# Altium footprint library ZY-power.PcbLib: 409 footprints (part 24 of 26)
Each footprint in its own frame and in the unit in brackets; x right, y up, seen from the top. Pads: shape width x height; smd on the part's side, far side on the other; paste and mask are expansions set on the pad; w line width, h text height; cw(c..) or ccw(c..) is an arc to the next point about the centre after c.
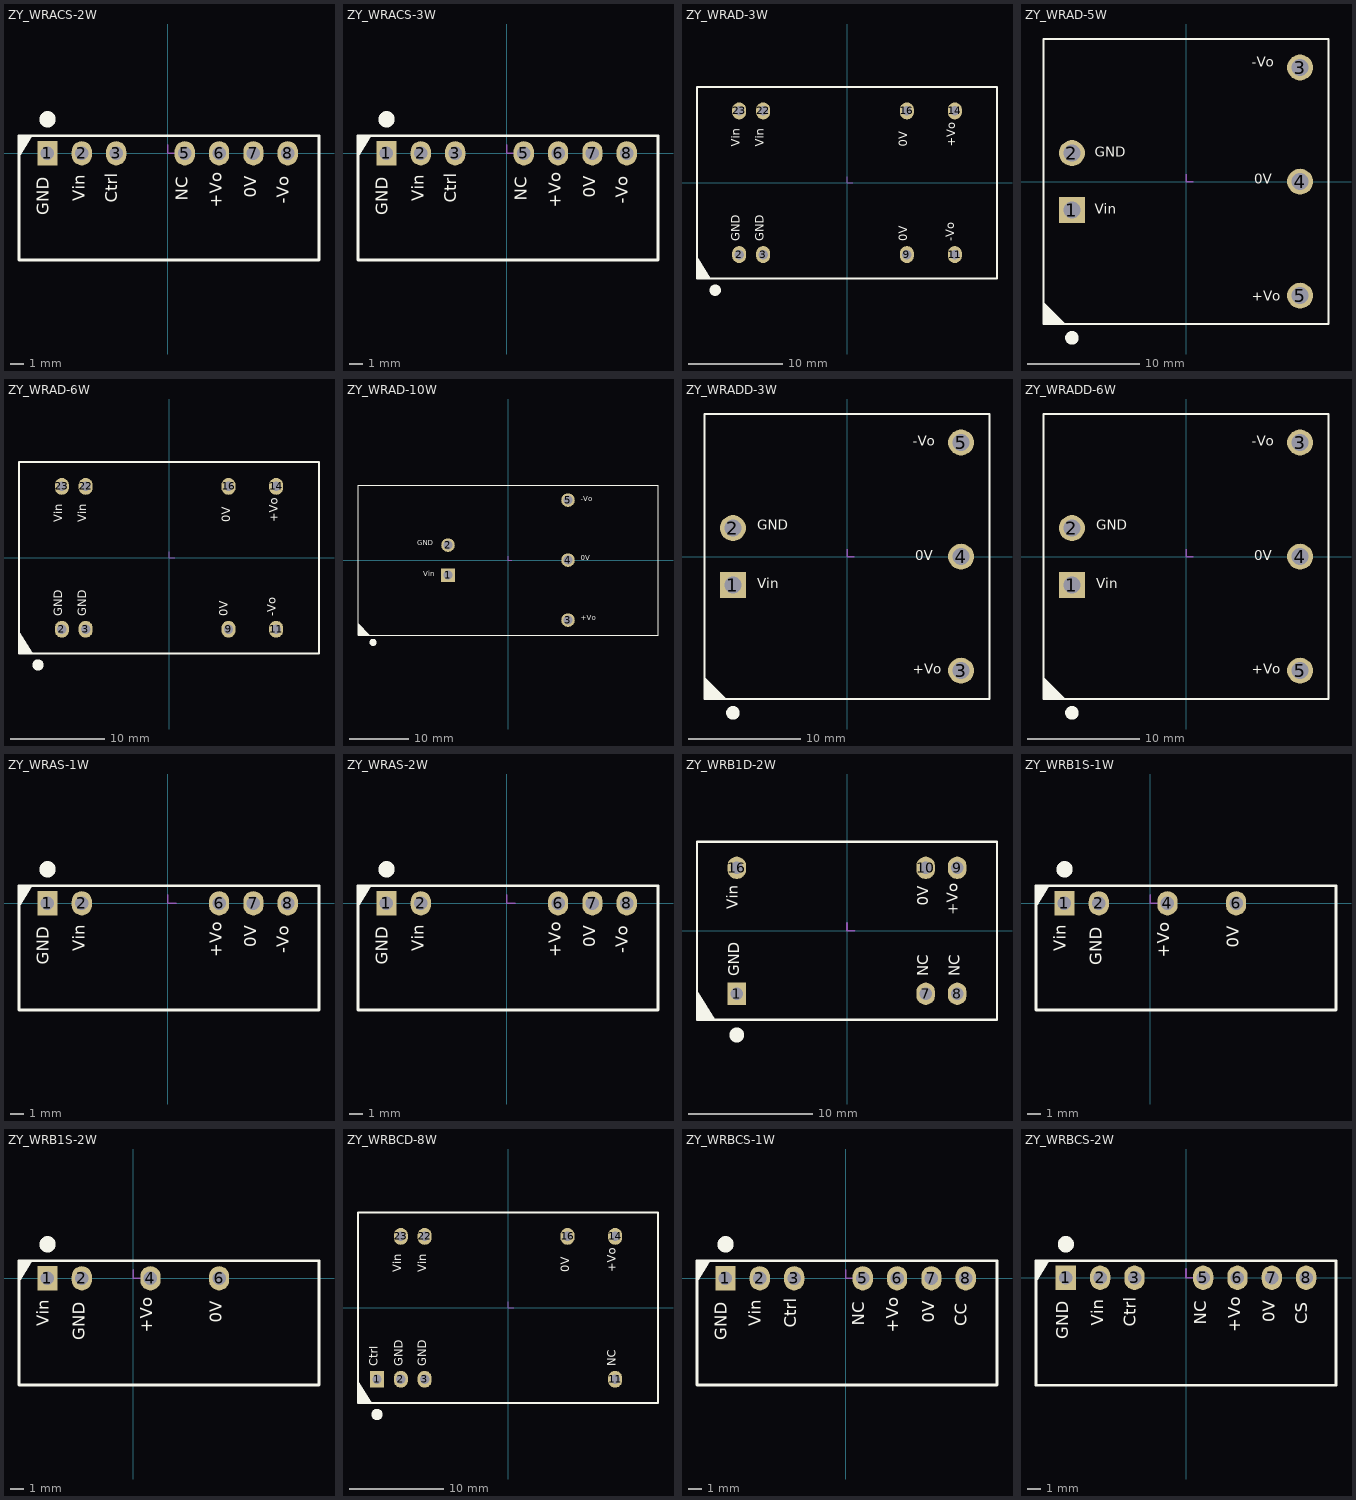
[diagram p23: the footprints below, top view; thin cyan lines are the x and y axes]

## ZY_WRACS-2W [mm]
pads (7):
  rect 1.5x1.8 hole 1: 1(-8.89,0)
  oval 1.5x1.8 hole 1: 2(-6.35,0) 3(-3.81,0) 5(1.27,0) 6(3.81,0) 7(6.35,0) 8(8.89,0)
Top Overlay:
  circle w1: c-8.89,2.52 r0.1
  region: -10.998,-0.29 -10.998,1.295 -10.005,1.295
  lines w0.2: 11.201,-7.899 -10.998,-7.899 -10.998,1.295 11.201,1.295 11.201,-7.874
  text "GND" at -8.509,-4.572 h1.52
  text "Vin" at -5.842,-3.562 h1.52
  text "Ctrl" at -3.429,-3.646 h1.52
  text "NC" at 1.778,-3.501 h1.52
  text "+Vo" at 4.318,-4.03 h1.52
  text "0V" at 6.858,-3.29 h1.52
  text "-Vo" at 9.271,-3.718 h1.52
Mechanical 15:
  lines w0.127: 0,0.635 0,0 0.635,0

## ZY_WRACS-3W [mm]
height 12.2
pads (7):
  rect 1.5x1.8 hole 1: 1(-8.89,0)
  oval 1.5x1.8 hole 1: 2(-6.35,0) 3(-3.81,0) 5(1.27,0) 6(3.81,0) 7(6.35,0) 8(8.89,0)
Top Overlay:
  circle w1: c-8.89,2.52 r0.1
  region: -10.998,-0.29 -10.998,1.295 -10.005,1.295
  lines w0.2: 11.201,-7.899 -10.998,-7.899 -10.998,1.295 11.201,1.295 11.201,-7.874
  text "-Vo" at 9.271,-3.718 h1.52
  text "0V" at 6.858,-3.29 h1.52
  text "+Vo" at 4.318,-4.03 h1.52
  text "NC" at 1.778,-3.501 h1.52
  text "Ctrl" at -3.429,-3.646 h1.52
  text "Vin" at -5.842,-3.562 h1.52
  text "GND" at -8.509,-4.572 h1.52
Mechanical 15:
  lines w0.127: 0,0.635 0,0 0.635,0

## ZY_WRAD-3W [mm]
pads (8):
  oval 1.5x1.8 hole 1: 2(-11.43,-7.62) 3(-8.89,-7.62) 9(6.35,-7.62) 11(11.43,-7.62) 14(11.43,7.62) 16(6.35,7.62) 22(-8.89,7.62) 23(-11.43,7.62)
Top Overlay:
  circle w1: c-13.97,-11.385 r0.1
  region: -15.9,-7.83 -15.9,-10.16 -14.44,-10.16
  lines w0.2: -15.9,-10.16 -15.9,10.16 15.9,10.16 15.9,-10.16 -15.9,-10.16
  text "Vin" at -11.049,3.81 h1.52
  text "Vin" at -8.509,3.81 h1.52
  text "0V" at 6.731,3.81 h1.52
  text "+Vo" at 11.811,3.81 h1.52
  text "-Vo" at 11.684,-6.223 h1.52
  text "0V" at 6.731,-6.223 h1.52
  text "GND" at -8.509,-6.223 h1.52
  text "GND" at -11.049,-6.223 h1.52
Mechanical 15:
  lines w0.127: 0,0.635 0,0 0.635,0

## ZY_WRAD-5W [mm]
height 11.7
pads (5):
  rect 2.3x2.3 hole 1.5: 1(-10.16,-2.54)
  round 2.3 hole 1.5: 2(-10.16,2.54) 3(10.16,10.16) 4(10.16,0) 5(10.16,-10.16)
Top Overlay:
  circle w1: c-10.16,-13.925 r0.1
  region: -12.7,-12.7 -10.725,-12.7 -12.7,-10.725
  lines w0.2: -12.7,-12.7 12.7,-12.7 12.7,12.7 -12.7,12.7 -12.7,-12.7
  text "-Vo" at 5.842,9.906 h1.52
  text "+Vo" at 5.842,-10.922 h1.52
  text "Vin" at -8.128,-3.175 h1.52
  text "GND" at -8.128,1.905 h1.52
  text "0V" at 6.096,-0.508 h1.52
Mechanical 15:
  lines w0.127: 0,0.635 0,0 0.635,0

## ZY_WRAD-6W [mm]
height 10.5
pads (8):
  oval 1.5x1.8 hole 1: 2(-11.43,-7.62) 3(-8.89,-7.62) 9(6.35,-7.62) 11(11.43,-7.62) 14(11.43,7.62) 16(6.35,7.62) 22(-8.89,7.62) 23(-11.43,7.62)
Top Overlay:
  circle w1: c-13.97,-11.425 r0.1
  region: -16,-7.87 -16,-10.2 -14.54,-10.2
  lines w0.2: -16,-10.2 16,-10.2 16,10.2 -16,10.2 -16,-10.2
  text "0V" at 6.858,3.81 h1.52
  text "+Vo" at 11.938,3.81 h1.52
  text "-Vo" at 11.684,-6.223 h1.52
  text "Vin" at -8.509,3.81 h1.52
  text "Vin" at -11.049,3.81 h1.52
  text "GND" at -8.509,-6.223 h1.52
  text "GND" at -11.049,-6.223 h1.52
  text "0V" at 6.604,-6.223 h1.52
Mechanical 15:
  lines w0.127: 0,0.635 0,0 0.635,0

## ZY_WRAD-10W [mm]
pads (5):
  rect 2.3x2.3 hole 1.5: 1(-10.16,-2.54)
  round 2.3 hole 1.5: 2(-10.16,2.54) 3(10.16,-10.16) 4(10.16,0) 5(10.16,10.16)
Top Overlay:
  circle w1: c-22.86,-13.925 r0.1
  region: -25.4,-12.7 -23.425,-12.7 -25.4,-10.725
  lines w0.2: -25.4,-12.7 25.4,-12.7 25.4,12.7 -25.4,12.7 -25.4,-12.7
  text "Vin" at -14.357,-3.048 h1.52
  text "GND" at -15.367,2.159 h1.52
  text "0V" at 12.319,-0.381 h1.52
  text "+Vo" at 12.319,-10.541 h1.52
  text "-Vo" at 12.319,9.652 h1.52
Mechanical 15:
  lines w0.127: 0,0.635 0,0 0.635,0

## ZY_WRADD-3W [mm]
height 11.7
pads (5):
  rect 2.3x2.3 hole 1.5: 1(-10.16,-2.54)
  round 2.3 hole 1.5: 2(-10.16,2.54) 3(10.16,-10.16) 4(10.16,0) 5(10.16,10.16)
Top Overlay:
  circle w1: c-10.16,-13.925 r0.1
  region: -12.7,-12.7 -10.725,-12.7 -12.7,-10.725
  lines w0.2: -12.7,-12.7 -12.7,12.7 12.7,12.7 12.7,-12.7 -12.7,-12.7
  text "0V" at 6.096,-0.635 h1.52
  text "GND" at -8.002,2.057 h1.52
  text "Vin" at -8.001,-3.15 h1.52
  text "+Vo" at 5.842,-10.744 h1.52
  text "-Vo" at 5.842,9.576 h1.52
Mechanical 15:
  lines w0.127: 0,0.635 0,0 0.635,0

## ZY_WRADD-6W [mm]
height 11.7
pads (5):
  rect 2.3x2.3 hole 1.5: 1(-10.16,-2.54)
  round 2.3 hole 1.5: 2(-10.16,2.54) 3(10.16,10.16) 4(10.16,0) 5(10.16,-10.16)
Top Overlay:
  circle w1: c-10.16,-13.925 r0.1
  region: -12.7,-12.7 -10.725,-12.7 -12.7,-10.725
  lines w0.2: -12.7,-12.7 12.7,-12.7 12.7,12.7 -12.7,12.7 -12.7,-12.7
  text "0V" at 6.096,-0.635 h1.52
  text "GND" at -8.001,2.057 h1.52
  text "Vin" at -8.001,-3.15 h1.52
  text "+Vo" at 5.842,-10.744 h1.52
  text "-Vo" at 5.842,9.576 h1.52
Mechanical 15:
  lines w0.127: 0,0.635 0,0 0.635,0

## ZY_WRAS-1W [mm]
height 12.2
pads (5):
  rect 1.5x1.8 hole 1: 1(-8.89,0)
  oval 1.5x1.8 hole 1: 2(-6.35,0) 6(3.81,0) 7(6.35,0) 8(8.89,0)
Top Overlay:
  circle w1: c-8.89,2.52 r0.1
  region: -10.998,-0.29 -10.998,1.295 -10.005,1.295
  lines w0.2: 11.201,-7.899 -10.998,-7.899 -10.998,1.295 11.201,1.295 11.201,-7.874
  text "-Vo" at 9.271,-3.692 h1.52
  text "0V" at 6.858,-3.264 h1.52
  text "+Vo" at 4.318,-4.004 h1.52
  text "Vin" at -5.842,-3.536 h1.52
  text "GND" at -8.509,-4.547 h1.52
Mechanical 15:
  lines w0.127: 0,0.635 0,0 0.635,0

## ZY_WRAS-2W [mm]
height 12.2
pads (5):
  rect 1.5x1.8 hole 1: 1(-8.89,0)
  oval 1.5x1.8 hole 1: 2(-6.35,0) 6(3.81,0) 7(6.35,0) 8(8.89,0)
Top Overlay:
  circle w1: c-8.89,2.52 r0.1
  region: -10.998,-0.29 -10.998,1.295 -10.005,1.295
  lines w0.2: 11.201,-7.899 -10.998,-7.899 -10.998,1.295 11.201,1.295 11.201,-7.874
  text "GND" at -8.509,-4.547 h1.52
  text "Vin" at -5.842,-3.536 h1.52
  text "+Vo" at 4.318,-4.004 h1.52
  text "0V" at 6.858,-3.264 h1.52
  text "-Vo" at 9.271,-3.692 h1.52
Mechanical 15:
  lines w0.127: 0,0.635 0,0 0.635,0

## ZY_WRB1D-2W [mm]
height 8.3
pads (6):
  rect 1.5x1.8 hole 1: 1(-8.89,-5.08)
  oval 1.5x1.8 hole 1: 7(6.35,-5.08) 8(8.89,-5.08) 9(8.89,5.08) 10(6.35,5.08) 16(-8.89,5.08)
Top Overlay:
  circle w1: c-8.89,-8.4 r0.1
  region: -12.1,-4.845 -12.1,-7.175 -10.64,-7.175
  lines w0.2: -12.1,-7.175 12.1,-7.175 12.1,7.175 -12.1,7.175 -12.1,-7.175
  text "NC" at 9.398,-3.683 h1.52
  text "GND" at -8.382,-3.683 h1.52
  text "Vin" at -8.509,1.738 h1.52
  text "0V" at 6.858,2.01 h1.52
  text "+Vo" at 9.271,1.27 h1.52
  text "NC" at 6.858,-3.683 h1.52
Mechanical 15:
  lines w0.127: 0,0.635 0,0 0.635,0

## ZY_WRB1S-1W [mm]
height 12.2
pads (4):
  rect 1.5x1.8 hole 1: 1(-6.35,0)
  oval 1.5x1.8 hole 1: 2(-3.81,0) 4(1.27,0) 6(6.35,0)
Top Overlay:
  circle w1: c-6.35,2.52 r0.1
  region: -8.458,-0.29 -8.458,1.295 -7.465,1.295
  lines w0.2: 13.741,-7.899 -8.458,-7.899 -8.458,1.295 13.741,1.295 13.741,-7.874
  text "Vin" at -5.969,-3.562 h1.52
  text "GND" at -3.302,-4.572 h1.52
  text "0V" at 6.858,-3.29 h1.52
  text "+Vo" at 1.702,-4.03 h1.52
Mechanical 15:
  lines w0.127: 0,0.635 0,0 0.635,0

## ZY_WRB1S-2W [mm]
height 12.2
pads (4):
  rect 1.5x1.8 hole 1: 1(-6.35,0)
  oval 1.5x1.8 hole 1: 2(-3.81,0) 4(1.27,0) 6(6.35,0)
Top Overlay:
  circle w1: c-6.35,2.52 r0.1
  region: -8.458,-0.29 -8.458,1.295 -7.465,1.295
  lines w0.2: 13.741,-7.899 -8.458,-7.899 -8.458,1.295 13.741,1.295 13.741,-7.874
  text "Vin" at -5.969,-3.562 h1.52
  text "GND" at -3.302,-4.572 h1.52
  text "0V" at 6.858,-3.29 h1.52
  text "+Vo" at 1.702,-4.03 h1.52
Mechanical 15:
  lines w0.127: 0,0.635 0,0 0.635,0

## ZY_WRBCD-8W [mm]
pads (8):
  rect 1.5x1.8 hole 1: 1(-13.97,-7.62)
  oval 1.5x1.8 hole 1: 2(-11.43,-7.62) 3(-8.89,-7.62) 11(11.43,-7.62) 14(11.43,7.62) 16(6.35,7.62) 22(-8.89,7.62) 23(-11.43,7.62)
Top Overlay:
  circle w1: c-13.97,-11.375 r0.1
  region: -16,-7.82 -16,-10.15 -14.54,-10.15
  lines w0.2: -16,-10.15 16,-10.15 16,10.15 -16,10.15 -16,-10.15
  text "Ctrl" at -13.589,-6.223 h1.52
  text "Vin" at -11.049,3.81 h1.52
  text "Vin" at -8.382,3.81 h1.52
  text "0V" at 6.858,3.81 h1.52
  text "+Vo" at 11.811,3.81 h1.52
  text "NC" at 11.811,-6.223 h1.52
  text "GND" at -8.382,-6.223 h1.52
  text "GND" at -10.922,-6.223 h1.52
Mechanical 15:
  lines w0.127: 0,0.635 0,0 0.635,0

## ZY_WRBCS-1W [mm]
height 12.2
pads (7):
  rect 1.5x1.8 hole 1: 1(-8.89,0)
  oval 1.5x1.8 hole 1: 2(-6.35,0) 3(-3.81,0) 5(1.27,0) 6(3.81,0) 7(6.35,0) 8(8.89,0)
Top Overlay:
  circle w1: c-8.89,2.52 r0.1
  region: -10.998,-0.29 -10.998,1.295 -10.005,1.295
  lines w0.2: 11.201,-7.899 -10.998,-7.899 -10.998,1.295 11.201,1.295 11.201,-7.874
  text "NC" at 1.676,-3.501 h1.52
  text "Ctrl" at -3.353,-3.646 h1.52
  text "GND" at -8.509,-4.572 h1.52
  text "Vin" at -5.969,-3.562 h1.52
  text "+Vo" at 4.191,-4.03 h1.52
  text "0V" at 6.858,-3.29 h1.52
  text "CC" at 9.271,-3.536 h1.52
Mechanical 15:
  lines w0.127: 0,0.635 0,0 0.635,0

## ZY_WRBCS-2W [mm]
height 12.2
pads (7):
  rect 1.5x1.8 hole 1: 1(-8.89,0)
  oval 1.5x1.8 hole 1: 2(-6.35,0) 3(-3.81,0) 5(1.27,0) 6(3.81,0) 7(6.35,0) 8(8.89,0)
Top Overlay:
  circle w1: c-8.89,2.475 r0.1
  region: -11.1,-0.336 -11.1,1.25 -10.106,1.25
  lines w0.2: -11.1,-7.95 11.1,-7.95 11.1,1.25 -11.1,1.25 -11.1,-7.95
  text "GND" at -8.399,-4.572 h1.52
  text "CS" at 9.279,-3.444 h1.52
  text "0V" at 6.866,-3.29 h1.52
  text "+Vo" at 4.326,-4.03 h1.52
  text "NC" at 1.786,-3.501 h1.52
  text "Ctrl" at -3.421,-3.646 h1.52
  text "Vin" at -5.834,-3.562 h1.52
Mechanical 15:
  lines w0.127: 0,0.635 0,0 0.635,0
3D body: height 12.2, standoff 0, extent -11.1,-7.95 11.1,1.25
3D body "zhenjao01.stp": height 8.36, standoff -4.08, extent 5.65,-1.48 7.05,0.12
3D body "zhenjao01.stp": height 8.36, standoff -4.08, extent 3.11,-1.48 4.51,0.12
3D body "zhenjao01.stp": height 8.36, standoff -4.08, extent 0.57,-1.48 1.97,0.12
3D body "zhenjao01.stp": height 8.36, standoff -4.08, extent -4.51,-1.48 -3.11,0.12
3D body "zhenjao01.stp": height 8.36, standoff -4.08, extent -7.05,-1.48 -5.65,0.12
3D body "zhenjao01.stp": height 8.36, standoff -4.08, extent -9.59,-1.48 -8.19,0.12
3D body "zhenjao01.stp": height 8.36, standoff -4.08, extent 8.19,-1.48 9.59,0.12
